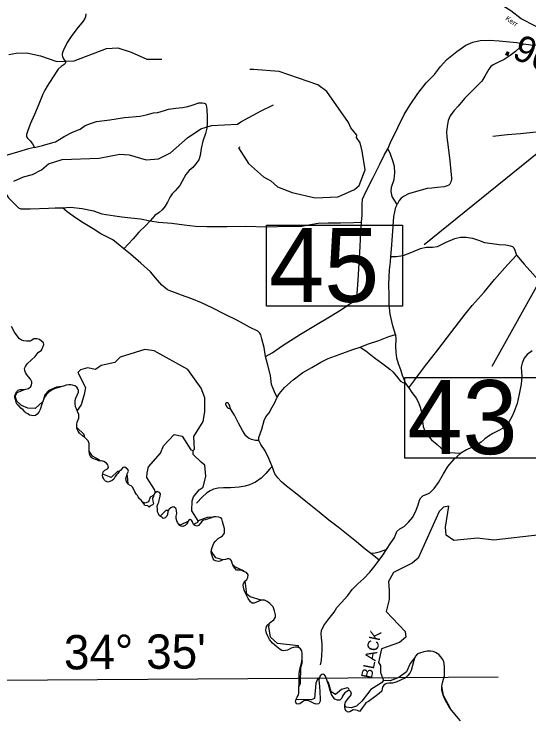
# Model space of a CAD drawing. Extents: x 2093524 to 2270757, y 289120 to 570408.
# Drawn here: x 2212810 to 2222555, y 303117 to 316455 of the extents above; entities that cross this region are included whole.
import ezdxf

# ---------------------------------------------------------------- set-up
doc = ezdxf.new("R2010")
doc.units = 0
for name, color, linetype in [('Exist Boundary Political CountyLine', 7, 'Continuous'), ('Exist Hydrographic Misc Water Feature', 7, 'Continuous'), ('Exist Hydrographic River Shore', 7, 'Continuous'), ('Exist Hydrographic River Shore Label', 7, 'Continuous'), ('Exist Road Non-System Type 51', 7, 'Continuous'), ('Exist Road Secondary Mileage Hundredths English Label', 7, 'Continuous'), ('Exist Road Secondary Structure Standard Bridge Number Label', 7, 'Continuous'), ('Exist Road Secondary Type 51 Attributed', 7, 'Continuous'), ('Exist Road Secondary Type 51 Label', 7, 'Continuous'), ('Map Preparation Longitude Latitude Label', 7, 'Continuous'), ('Map Preparation Longitude Latitude Lines', 7, 'Continuous')]:
    doc.layers.add(name, color=color, linetype=linetype)

msp = doc.modelspace()

# ---------------------------------------------------------------- linework, layer by layer
at = {"layer": 'Exist Boundary Political CountyLine'}
for points in [[(2214036, 308841), (2214036, 308876), (2214013, 308932), (2213989, 308986), (2213975, 309024), (2213966, 309088), (2213966, 309137), (2213970, 309175), (2214007, 309246), (2214028, 309299), (2214030, 309333), (2214018, 309365), (2213998, 309395), (2213957, 309423), (2213917, 309431), (2213884, 309437), (2213847, 309440), (2213795, 309431), (2213746, 309415), (2213696, 309399), (2213639, 309385), (2213588, 309373), (2213544, 309350), (2213470, 309303), (2213418, 309251), (2213388, 309207), (2213358, 309142), (2213337, 309072), (2213305, 308971), (2213280, 308920), (2213249, 308883), (2213216, 308860), (2213178, 308854), (2213138, 308859), (2213102, 308868), (2213069, 308888), (2213032, 308912), (2213012, 308931), (2212980, 308967), (2212940, 309001), (2212904, 309038), (2212869, 309070), (2212850, 309104), (2212843, 309140), (2212828, 309174), (2212823, 309203), (2212824, 309232), (2212843, 309275), (2212856, 309308), (2212890, 309340), (2212922, 309351), (2212962, 309351), (2213031, 309356), (2213083, 309371), (2213124, 309411), (2213139, 309440), (2213145, 309469), (2213144, 309498), (2213122, 309544), (2213081, 309590), (2213044, 309640), (2213025, 309674), (2213011, 309710), (2213009, 309747), (2213028, 309784), (2213060, 309836), (2213141, 309911), (2213209, 309976), (2213265, 310049), (2213330, 310098), (2213357, 310150), (2213375, 310202), (2213365, 310237), (2213330, 310267), (2213294, 310297), (2213248, 310313), (2213218, 310313), (2213184, 310307), (2213140, 310280), (2213112, 310267), (2213080, 310264), (2213047, 310263), (2212996, 310269), (2212952, 310283), (2212914, 310310), (2212888, 310344), (2212816, 310437), (2212764, 310543)], [(2213995, 308642), (2214000, 308694), (2214007, 308734), (2214035, 308808), (2214036, 308841)], [(2215893, 307003), (2215885, 307057), (2215876, 307095), (2215833, 307129), (2215801, 307123), (2215774, 307110), (2215745, 307084), (2215719, 307042), (2215711, 306983), (2215702, 306956), (2215671, 306921), (2215635, 306913), (2215610, 306930), (2215559, 306966), (2215541, 306998), (2215526, 307036), (2215524, 307084), (2215521, 307142), (2215528, 307184), (2215547, 307220), (2215554, 307258), (2215578, 307332), (2215580, 307379), (2215561, 307405), (2215516, 307421), (2215473, 307387), (2215458, 307364), (2215447, 307335), (2215433, 307286), (2215434, 307237), (2215447, 307190), (2215427, 307168), (2215382, 307142), (2215366, 307127), (2215343, 307150), (2215288, 307159), (2215257, 307202), (2215234, 307230), (2215214, 307254), (2215181, 307285), (2215161, 307317), (2215144, 307343), (2215124, 307367), (2215097, 307413), (2215056, 307494), (2215024, 307526), (2214996, 307540), (2214973, 307560), (2214938, 307603), (2214929, 307635), (2214926, 307668), (2214936, 307706), (2214952, 307757), (2214973, 307807), (2214962, 307839), (2214907, 307882), (2214870, 307876), (2214828, 307826), (2214800, 307797), (2214771, 307763), (2214747, 307734), (2214724, 307702), (2214701, 307654), (2214664, 307627), (2214620, 307613), (2214588, 307595), (2214542, 307615), (2214521, 307635), (2214506, 307662), (2214488, 307693), (2214486, 307725), (2214488, 307755), (2214498, 307791), (2214525, 307823), (2214578, 307852), (2214596, 307874), (2214587, 307924), (2214558, 307956), (2214508, 307990), (2214470, 307999), (2214440, 307996), (2214413, 308002), (2214379, 308018), (2214349, 308025), (2214289, 308051), (2214265, 308071), (2214248, 308097), (2214237, 308135), (2214228, 308187), (2214228, 308239), (2214232, 308288), (2214231, 308332), (2214210, 308377), (2214176, 308420), (2214146, 308444), (2214104, 308477), (2214046, 308523), (2214022, 308562), (2214000, 308613), (2213995, 308642)], [(2217848, 304432), (2217784, 304482), (2217702, 304548), (2217645, 304623), (2217613, 304682), (2217588, 304740), (2217576, 304797), (2217579, 304832), (2217588, 304869), (2217613, 304896), (2217660, 304941), (2217729, 304994), (2217756, 305040), (2217756, 305089), (2217737, 305160), (2217712, 305236), (2217652, 305302), (2217600, 305342), (2217550, 305365), (2217486, 305362), (2217354, 305307), (2217315, 305310), (2217283, 305336), (2217240, 305393), (2217218, 305447), (2217164, 305555), (2217154, 305610), (2217148, 305647), (2217154, 305683), (2217181, 305722), (2217218, 305756), (2217236, 305793), (2217242, 305842), (2217212, 305886), (2217174, 305903), (2217123, 305927), (2217074, 305933), (2217022, 305935), (2216999, 305956), (2216966, 305999), (2216937, 306065), (2216928, 306110), (2216905, 306131), (2216879, 306144), (2216852, 306147), (2216812, 306136), (2216760, 306125), (2216714, 306102), (2216679, 306098), (2216650, 306102), (2216622, 306110), (2216595, 306124), (2216577, 306145), (2216564, 306183), (2216548, 306241), (2216538, 306280), (2216545, 306318), (2216557, 306362), (2216594, 306443), (2216622, 306484), (2216672, 306531), (2216720, 306554), (2216758, 306581), (2216790, 306635), (2216792, 306675), (2216793, 306721), (2216773, 306782), (2216758, 306850), (2216740, 306906), (2216716, 306924), (2216686, 306936), (2216631, 306942), (2216588, 306939), (2216544, 306925), (2216503, 306912), (2216469, 306896), (2216425, 306887), (2216396, 306876), (2216371, 306864), (2216344, 306829), (2216300, 306779), (2216275, 306763), (2216229, 306779), (2216206, 306795), (2216188, 306846), (2216171, 306876), (2216144, 306893), (2216110, 306872), (2216096, 306838), (2216078, 306811), (2216047, 306776), (2216002, 306760), (2215971, 306763), (2215948, 306779), (2215924, 306808), (2215902, 306837), (2215893, 306866), (2215879, 306913), (2215879, 306953), (2215893, 307003)], [(2220632, 304399), (2220564, 304388), (2220484, 304362), (2220440, 304341), (2220412, 304309), (2220392, 304267), (2220376, 304220), (2220354, 304130), (2220329, 304032), (2220300, 303980), (2220266, 303942), (2220220, 303897), (2220042, 303812), (2219974, 303795), (2219902, 303796), (2219861, 303785), (2219832, 303773), (2219810, 303756), (2219786, 303721), (2219780, 303692), (2219774, 303643), (2219718, 303596), (2219639, 303536), (2219517, 303444), (2219470, 303422), (2219440, 303381), (2219404, 303335), (2219374, 303291), (2219350, 303258), (2219308, 303277), (2219282, 303284), (2219229, 303288), (2219168, 303249), (2219132, 303242), (2219090, 303269), (2219074, 303303), (2219070, 303343), (2219073, 303391), (2219082, 303437), (2219136, 303503), (2219178, 303552), (2219194, 303587), (2219186, 303630), (2219160, 303657), (2219126, 303650), (2219072, 303612), (2219048, 303582), (2219026, 303547), (2219012, 303508), (2218974, 303469), (2218930, 303472), (2218884, 303490), (2218858, 303521), (2218818, 303582), (2218796, 303657), (2218760, 303770), (2218706, 303925), (2218671, 303965), (2218638, 303960), (2218602, 303933), (2218579, 303858), (2218590, 303729), (2218596, 303628), (2218606, 303492), (2218603, 303455), (2218576, 303404), (2218527, 303395), (2218492, 303412), (2218414, 303446), (2218369, 303463), (2218305, 303464), (2218272, 303441), (2218216, 303401), (2218163, 303398), (2218138, 303441), (2218149, 303492), (2218168, 303528), (2218186, 303563), (2218200, 303603), (2218198, 303696), (2218204, 303797), (2218209, 303898), (2218208, 303969), (2218219, 304058), (2218242, 304145), (2218260, 304234), (2218263, 304354), (2218258, 304403), (2218233, 304442), (2218206, 304465), (2218169, 304474), (2218140, 304476), (2218102, 304471), (2218058, 304458), (2218008, 304430), (2217986, 304416), (2217948, 304410), (2217912, 304403), (2217877, 304410), (2217848, 304432)], [(2221258, 303082), (2221214, 303134), (2221097, 303278), (2221054, 303332), (2221002, 303422), (2220948, 303515), (2220925, 303584), (2220910, 303665), (2220909, 303739), (2220920, 303799), (2220938, 303868), (2220955, 303935), (2220958, 304004), (2220955, 304112), (2220945, 304202), (2220920, 304249), (2220885, 304293), (2220848, 304335), (2220790, 304376), (2220740, 304393), (2220697, 304400), (2220632, 304399)]]:
    msp.add_lwpolyline(points, dxfattribs=at)
at = {"layer": 'Exist Hydrographic Misc Water Feature'}
for points in [[(2212708, 315692), (2212849, 315719), (2213050, 315721), (2213308, 315664), (2213617, 315556), (2213950, 315569), (2214557, 315806), (2214773, 315815), (2215024, 315735), (2215324, 315601), (2215608, 315605)], [(2217085, 313939), (2217060, 313923), (2217246, 313631), (2217531, 313376), (2217673, 313301), (2217798, 313187), (2218074, 313080), (2218508, 312976), (2218941, 312994), (2218955, 313001), (2219256, 313139), (2219339, 313213), (2219454, 313506), (2219402, 313864), (2219359, 314022), (2219294, 314117), (2219291, 314122), (2219299, 314165), (2219182, 314305), (2219140, 314404), (2218727, 314993), (2218560, 315117), (2217825, 315368), (2217342, 315407), (2217275, 315408)], [(2212808, 313294), (2212991, 313377), (2213157, 313420), (2213331, 313505), (2213464, 313624), (2213722, 313701), (2214421, 313730), (2214812, 313807), (2214987, 313791), (2215313, 313696), (2215546, 313714), (2215770, 313831), (2216093, 314116), (2216342, 314285), (2216549, 314344), (2217041, 314373), (2217099, 314415), (2217489, 314627), (2217721, 314737)], [(2216255, 309509), (2216098, 309727), (2215462, 310081), (2215287, 310111), (2214821, 309966), (2214714, 309860), (2214456, 309806), (2214349, 309732), (2214198, 309762), (2214065, 309722), (2214016, 309670), (2214159, 309388), (2214135, 309254), (2214078, 309062), (2214004, 308955)], [(2216200, 308194), (2216225, 308219), (2216215, 308462), (2216388, 308744), (2216420, 308927), (2216418, 309196), (2216350, 309378), (2216255, 309509)], [(2213716, 309405), (2213610, 309393), (2213468, 309333), (2213393, 309249), (2213352, 309125), (2213212, 308990), (2213071, 308997), (2212953, 309048), (2212862, 309129), (2212828, 309228), (2212869, 309296), (2213027, 309356)], [(2214004, 308955), (2213999, 308963)], [(2214004, 308953), (2214004, 308955)], [(2214151, 308440), (2214139, 308497), (2213997, 308629)], [(2215322, 307688), (2215328, 307771), (2215353, 307889), (2215584, 308147), (2215641, 308283), (2215840, 308499), (2215990, 308467), (2216158, 308211), (2216200, 308194)], [(2214443, 307995), (2214419, 308022), (2214293, 308090), (2214243, 308163), (2214229, 308184)], [(2216293, 306863), (2216175, 307053), (2216182, 307246), (2216206, 307321), (2216313, 307453), (2216388, 307504), (2216437, 307713), (2216419, 307920), (2216354, 307978), (2216200, 308118), (2216200, 308194)], [(2214810, 307807), (2214770, 307802), (2214646, 307683), (2214488, 307748)], [(2214967, 307565), (2214954, 307720), (2214945, 307734)], [(2215484, 307397), (2215471, 307457), (2215322, 307688)], [(2215453, 307353), (2215389, 307314), (2215357, 307223), (2215291, 307198), (2215245, 307217)], [(2215730, 307059), (2215682, 307059), (2215578, 306952)], [(2216574, 306935), (2216467, 306929), (2216293, 306863)], [(2216101, 306850), (2215952, 306785), (2215934, 306795)], [(2216293, 306863), (2216284, 306837), (2216207, 306795)], [(2216546, 306287), (2216548, 306329)], [(2216764, 306126), (2216631, 306164), (2216546, 306287)], [(2217165, 305907), (2217165, 305911), (2216989, 305993), (2216952, 306029)], [(2217485, 305362), (2217277, 305427), (2217218, 305477), (2217187, 305728)], [(2218199, 304467), (2218191, 304500), (2217799, 304547), (2217665, 304665), (2217631, 304862), (2217646, 304927)], [(2220693, 304400), (2220691, 304402), (2220685, 304400)], [(2220398, 304281), (2220309, 304166), (2220235, 304007), (2220095, 303898), (2219929, 303839), (2219803, 303845)], [(2218200, 303724), (2218229, 303794), (2218236, 304092), (2218268, 304194), (2218259, 304228)], [(2218584, 303893), (2218562, 303879), (2218521, 303795), (2218498, 303503), (2218431, 303479), (2218157, 303484)], [(2219803, 303845), (2219762, 303797), (2219563, 303676), (2219390, 303450), (2219290, 303360), (2219191, 303326), (2219099, 303341), (2219071, 303368)], [(2219152, 303658), (2219146, 303691), (2219113, 303708), (2219005, 303674), (2218897, 303581), (2218814, 303632), (2218762, 303807), (2218739, 303830)], [(2221068, 303313), (2220938, 303560), (2220908, 303736)], [(2218157, 303484), (2218156, 303506)]]:
    msp.add_lwpolyline(points, dxfattribs=at)
at = {"layer": 'Exist Hydrographic River Shore'}
msp.add_lwpolyline([(2222767, 306598), (2221893, 306500), (2221584, 306539), (2221135, 306495), (2220992, 306593), (2220975, 306745), (2221039, 307144), (2220939, 307126), (2220856, 307042), (2220462, 306158), (2220346, 306065), (2219989, 305888), (2219899, 305719), (2219908, 305545), (2219909, 305378), (2219853, 305153), (2220214, 304772), (2220223, 304663), (2220107, 304564), (2219766, 304446), (2219709, 304185), (2219743, 304128), (2219744, 303994), (2219803, 303845)], dxfattribs=at)
at = {"layer": 'Exist Road Non-System Type 51'}
msp.add_line((2220222, 309467), (2220281, 309384), dxfattribs=at)
for points in [[(2214165, 316459), (2214164, 316403), (2214152, 316369), (2214117, 316319), (2213998, 316175), (2213891, 316029), (2213814, 315916), (2213737, 315762), (2213725, 315731), (2213722, 315698), (2213721, 315678), (2213727, 315652), (2213748, 315607), (2213774, 315567), (2213782, 315554), (2213785, 315537), (2213779, 315518), (2213761, 315499), (2213702, 315462), (2213647, 315413), (2213534, 315247), (2213435, 315092), (2213390, 315013), (2213351, 314939), (2213278, 314753), (2213194, 314556), (2213115, 314375), (2213061, 314232), (2213044, 314179), (2213042, 314161), (2213044, 314142), (2213050, 314125), (2213061, 314108), (2213114, 314055), (2213161, 314000), (2213194, 313932)], [(2222451, 315894), (2222590, 315871), (2222704, 315867), (2222803, 315878), (2222921, 315910), (2223036, 315948), (2223149, 315988)], [(2219882, 313908), (2219938, 314027), (2220077, 314307), (2220195, 314555), (2220306, 314737), (2220450, 314953), (2220609, 315152), (2220766, 315314), (2220879, 315464), (2220999, 315596), (2221188, 315745), (2221362, 315866), (2221495, 315926), (2221632, 315955), (2221808, 315959), (2221991, 315949), (2222187, 315928), (2222327, 315916), (2222451, 315894)], [(2222451, 315894), (2222390, 315827), (2222302, 315750), (2222201, 315670), (2222088, 315598), (2221965, 315538), (2221876, 315493), (2221837, 315464), (2221796, 315414), (2221720, 315279), (2221662, 315189), (2221534, 315053), (2221335, 314856), (2221216, 314710), (2221133, 314625), (2221063, 314530), (2221027, 314439), (2221009, 314327), (2220996, 314229), (2221002, 314124), (2221029, 313936), (2221058, 313678), (2221079, 313475), (2221089, 313355), (2221088, 313315), (2221079, 313286), (2221071, 313260), (2221057, 313239), (2221039, 313221), (2221011, 313208), (2220949, 313188), (2220820, 313174), (2220718, 313163), (2220631, 313155), (2220430, 313100), (2220277, 313051), (2220191, 313010), (2220136, 312969), (2220099, 312930), (2220064, 312850)], [(2223896, 315253), (2223884, 315125), (2223885, 314948), (2223891, 314710), (2223895, 314562), (2223897, 314462), (2223902, 314384), (2223902, 314360), (2223897, 314340), (2223890, 314322), (2223878, 314308), (2223860, 314301), (2223818, 314295), (2223648, 314284), (2223386, 314267), (2223085, 314248), (2222748, 314225), (2222398, 314189), (2222151, 314170), (2221875, 314138)], [(2213194, 313932), (2213346, 313969), (2213501, 314012), (2213596, 314041), (2213759, 314136), (2213913, 314218), (2214058, 314279), (2214153, 314344), (2214276, 314393), (2214372, 314422), (2214625, 314454), (2214898, 314497), (2215196, 314524), (2215313, 314546), (2215446, 314588), (2215532, 314596), (2215660, 314628), (2215735, 314653), (2215869, 314675), (2215996, 314686), (2216102, 314709), (2216202, 314735), (2216307, 314775), (2216329, 314778), (2216373, 314776), (2216409, 314772), (2216429, 314765), (2216442, 314751), (2216449, 314731), (2216461, 314655), (2216465, 314514), (2216467, 314390), (2216461, 314294), (2216431, 314195), (2216381, 314051), (2216352, 313912), (2216332, 313782), (2216305, 313699), (2216252, 313623), (2216196, 313550), (2216121, 313494), (2216058, 313421), (2215990, 313296), (2215948, 313210), (2215859, 313112), (2215804, 313051), (2215763, 312995), (2215717, 312896), (2215672, 312823), (2215610, 312752), (2215554, 312699), (2215475, 312646), (2215387, 312545)], [(2213194, 313932), (2213081, 313906), (2212872, 313845), (2212633, 313773), (2212434, 313714), (2212335, 313688), (2212264, 313659), (2212192, 313618)], [(2219386, 312515), (2219398, 312653), (2219402, 312849), (2219407, 312953), (2219472, 313104), (2219600, 313348), (2219733, 313614), (2219814, 313785), (2219882, 313908)], [(2220064, 312850), (2220017, 312919), (2219967, 313004), (2219946, 313097), (2219952, 313182), (2220002, 313327), (2220020, 313449), (2220012, 313570), (2219988, 313660), (2219927, 313825), (2219882, 313908)], [(2212298, 313515), (2212363, 313459), (2212428, 313388), (2212505, 313299), (2212620, 313135), (2212668, 313034), (2212707, 312979), (2212800, 312884), (2212853, 312829), (2212892, 312792), (2212940, 312771), (2213116, 312770), (2213464, 312784), (2213588, 312788), (2213724, 312792)], [(2213724, 312792), (2213876, 312801), (2214098, 312778), (2214314, 312730), (2214469, 312677), (2214716, 312637), (2214848, 312617), (2215018, 312598), (2215201, 312579), (2215387, 312545)], [(2214890, 312013), (2214779, 312104), (2214678, 312185), (2214452, 312297), (2214306, 312394), (2214120, 312505), (2213971, 312599), (2213813, 312714), (2213724, 312792)], [(2219943, 311870), (2219952, 312007), (2219976, 312257), (2219987, 312445), (2220000, 312623), (2220016, 312713), (2220037, 312803), (2220064, 312850)], [(2215387, 312545), (2215301, 312453), (2215173, 312327), (2215061, 312205), (2214967, 312104), (2214890, 312013)], [(2215387, 312545), (2215542, 312519), (2215796, 312500), (2216032, 312468), (2216241, 312443), (2216459, 312437), (2216843, 312435), (2217190, 312439), (2217600, 312432), (2217996, 312441), (2218146, 312441), (2218254, 312443), (2218423, 312474), (2218565, 312501), (2218755, 312506), (2218988, 312502), (2219236, 312512), (2219386, 312515)], [(2217572, 309977), (2217693, 310043), (2217904, 310193), (2218231, 310400), (2218514, 310567), (2218783, 310727), (2219006, 310867), (2219208, 311003), (2219253, 311036), (2219280, 311067), (2219296, 311105), (2219307, 311166), (2219325, 311420), (2219339, 311744), (2219362, 312058), (2219375, 312334), (2219386, 312515)], [(2219943, 311870), (2220045, 311866), (2220178, 311888), (2220341, 311953), (2220504, 312020), (2220608, 312044), (2220728, 312044), (2220823, 312059), (2220988, 312140), (2221150, 312211), (2221258, 312235), (2221368, 312234), (2221488, 312218), (2221599, 312176), (2221714, 312130), (2221860, 312111), (2221990, 312093), (2222116, 312091), (2222204, 312073), (2222245, 312059), (2222273, 312034), (2222290, 311990), (2222304, 311950), (2222322, 311893)], [(2217572, 309977), (2217541, 310147), (2217500, 310310), (2217481, 310388), (2217463, 310415), (2217424, 310456), (2217265, 310532), (2217037, 310654), (2216793, 310778), (2216557, 310897), (2216359, 310994), (2216172, 311065), (2215981, 311134), (2215868, 311182), (2215780, 311212), (2215717, 311237), (2215667, 311274), (2215606, 311323), (2215524, 311422), (2215390, 311577), (2215211, 311740), (2215016, 311911), (2214890, 312013)], [(2220028, 310395), (2219981, 310556), (2219931, 310775), (2219912, 310957), (2219908, 311128), (2219906, 311342), (2219917, 311618), (2219937, 311768), (2219943, 311870)], [(2220281, 309384), (2220394, 309531), (2220582, 309779), (2220831, 310103), (2221095, 310451), (2221347, 310775), (2221480, 310939), (2221706, 311193), (2221903, 311430), (2222153, 311710), (2222322, 311893)], [(2222322, 311893), (2222466, 311723), (2222792, 311357), (2222980, 311138), (2223140, 310917), (2223289, 310730), (2223410, 310560), (2223518, 310406), (2223580, 310313)], [(2219360, 310150), (2219503, 310206), (2219716, 310281), (2219901, 310355), (2220028, 310395)], [(2220028, 310395), (2220037, 310301), (2220030, 310171), (2220034, 310051), (2220047, 309949), (2220079, 309844), (2220125, 309729), (2220155, 309625), (2220186, 309544), (2220222, 309467)], [(2217787, 309204), (2217834, 309278), (2217928, 309390), (2218095, 309531), (2218273, 309675), (2218445, 309768), (2218616, 309867), (2218756, 309935), (2218965, 310011), (2219221, 310105), (2219360, 310150)], [(2219360, 310150), (2219471, 310084), (2219627, 309956), (2219789, 309835), (2219868, 309780), (2219923, 309739), (2219980, 309686), (2220047, 309604), (2220094, 309546), (2220125, 309507), (2220167, 309486), (2220222, 309467)], [(2217787, 309204), (2217750, 309273), (2217685, 309445), (2217662, 309615), (2217606, 309838), (2217572, 309977)], [(2222616, 310083), (2222523, 310011), (2222467, 309941), (2222430, 309850), (2222409, 309776), (2222415, 309684), (2222423, 309588), (2222407, 309454), (2222372, 309265), (2222335, 309087), (2222276, 308932), (2222230, 308837), (2222183, 308747), (2222132, 308678), (2222053, 308614), (2221972, 308567), (2221875, 308519), (2221790, 308470), (2221723, 308419), (2221654, 308356), (2221563, 308300), (2221466, 308253), (2221373, 308211), (2221266, 308145)], [(2220281, 309384), (2220342, 309293), (2220426, 309180), (2220470, 309089), (2220499, 309018), (2220534, 308876), (2220542, 308752), (2220555, 308649), (2220589, 308549), (2220648, 308474), (2220712, 308398), (2220819, 308313), (2220896, 308241), (2220947, 308200), (2220985, 308170), (2221056, 308160), (2221159, 308155), (2221266, 308145)], [(2217443, 308384), (2217446, 308442), (2217498, 308599), (2217543, 308764), (2217575, 308834), (2217640, 308911), (2217698, 309016), (2217743, 309105), (2217787, 309204)], [(2216909, 308985), (2216888, 309052), (2216878, 309073), (2216866, 309088), (2216852, 309099), (2216838, 309101), (2216825, 309097), (2216820, 309092), (2216814, 309082), (2216813, 309071), (2216818, 309053), (2216824, 309039), (2216834, 309023), (2216848, 309010), (2216869, 308998), (2216909, 308985)], [(2217443, 308384), (2217379, 308385), (2217301, 308402), (2217247, 308427), (2217196, 308476), (2217134, 308577), (2217060, 308715), (2216981, 308866), (2216909, 308985)], [(2217697, 307895), (2217635, 308044), (2217560, 308188), (2217480, 308313), (2217443, 308384)], [(2219857, 306326), (2219939, 306448), (2220002, 306539), (2220034, 306615), (2220057, 306666), (2220115, 306717), (2220192, 306760), (2220276, 306841), (2220361, 306933), (2220418, 307068), (2220461, 307166), (2220487, 307257), (2220510, 307300), (2220548, 307338), (2220654, 307382), (2220678, 307396), (2220707, 307418), (2220765, 307477), (2220843, 307594), (2220940, 307754), (2221022, 307891), (2221140, 308033), (2221266, 308145)], [(2217697, 307895), (2217644, 307842), (2217578, 307759), (2217487, 307675), (2217382, 307600), (2217268, 307546), (2217182, 307520), (2217068, 307500), (2216909, 307490), (2216771, 307493), (2216670, 307483), (2216587, 307462), (2216520, 307433), (2216451, 307392), (2216376, 307323), (2216266, 307199)], [(2219561, 306247), (2219455, 306330), (2219291, 306467), (2219131, 306592), (2218944, 306743), (2218770, 306878), (2218582, 307032), (2218330, 307230), (2218132, 307394), (2217968, 307524), (2217874, 307602), (2217801, 307677), (2217746, 307758), (2217697, 307895)], [(2219857, 306326), (2219792, 306295), (2219718, 306270), (2219643, 306257), (2219561, 306247)], [(2219723, 306120), (2219650, 306177), (2219561, 306247)], [(2219723, 306120), (2219793, 306215), (2219857, 306326)], [(2218613, 304143), (2218632, 304223), (2218640, 304423), (2218644, 304541), (2218626, 304649), (2218621, 304728), (2218632, 304793), (2218674, 304883), (2218768, 305009), (2218866, 305138), (2218922, 305223), (2219005, 305319), (2219126, 305451), (2219212, 305568), (2219315, 305676), (2219429, 305776), (2219541, 305895), (2219619, 305987), (2219723, 306120)]]:
    msp.add_lwpolyline(points, dxfattribs=at)
at = {"layer": 'Exist Road Secondary Structure Standard Bridge Number Label'}
for p, q in [((2224237, 315053), (2220572, 312086)), ((2224790, 315053), (2221852, 309788))]:
    msp.add_line(p, q, dxfattribs=at)
for points in [[(2217589, 312458), (2220165, 312458), (2220165, 310929), (2217589, 310929)], [(2220207, 309578), (2222784, 309578), (2222784, 308049), (2220207, 308049)]]:
    msp.add_lwpolyline(points, close=True, dxfattribs=at)
at = {"layer": 'Exist Road Secondary Type 51 Attributed'}
msp.add_lwpolyline([(2224249, 315527), (2224162, 315544), (2223971, 315611), (2222956, 316079), (2222678, 316224), (2222410, 316366), (2222215, 316516), (2222062, 316609)], dxfattribs=at)
at = {"layer": 'Map Preparation Longitude Latitude Lines'}
msp.add_line((2212479, 303848), (2221972, 303915), dxfattribs=at)

# ---------------------------------------------------------------- texts
at = {"layer": 'Exist Hydrographic River Shore Label'}
msp.add_text('BLACK', height=210, rotation=78.3639, dxfattribs=at).set_placement((2219580, 303866))
at = {"layer": 'Exist Road Secondary Mileage Hundredths English Label'}
msp.add_text('.90', height=500, rotation=335.6465, dxfattribs=at).set_placement((2222047, 315709))
at = {"layer": 'Exist Road Secondary Structure Standard Bridge Number Label'}
for s, p in [('45', (2217639, 311008)), ('43', (2220257, 308128))]:
    msp.add_text(s, height=1400, dxfattribs=at).set_placement(p)
at = {"layer": 'Exist Road Secondary Type 51 Label'}
msp.add_text('Kerr', height=95, rotation=325.9967, dxfattribs=at).set_placement((2222101, 316350))
at = {"layer": 'Map Preparation Longitude Latitude Label'}
msp.add_text("34° 35'", height=650, rotation=0.4088, dxfattribs=at).set_placement((2213755, 304053))

doc.saveas('drawing.dxf')
